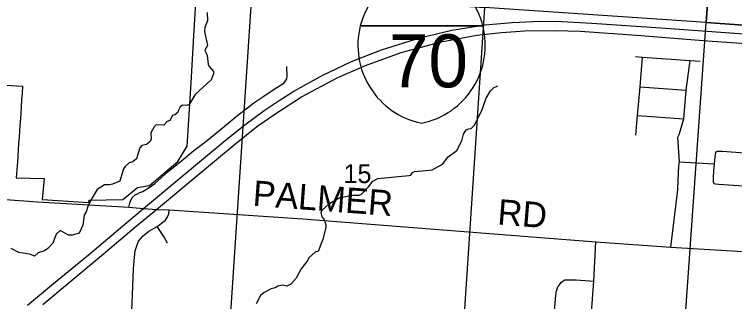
# Model space of a CAD drawing. Extents: x 0 to 34, y 0 to 22.
# Drawn here: x 4.853 to 6.46, y 18.458 to 19.099 of the extents above; entities that cross this region are included whole.
import ezdxf

# ---------------------------------------------------------------- set-up
doc = ezdxf.new("R2010")
doc.units = 0
for name, color, linetype in [('GM_X_Corporation', 7, 'Continuous'), ('GM_X_Interstate_Location', 7, 'Continuous'), ('GM_X_Interstate_Route', 7, 'Continuous'), ('GM_X_Interstate_Shield', 7, 'Continuous'), ('GM_X_Minor_River', 7, 'Continuous'), ('GM_X_Section_Text', 7, 'Continuous'), ('GM_X_Township_Road', 7, 'Continuous'), ('GM_X_Township_Road_Text', 7, 'Continuous')]:
    doc.layers.add(name, color=color, linetype=linetype)

msp = doc.modelspace()

# ---------------------------------------------------------------- linework, layer by layer
at = {"layer": 'GM_X_Corporation'}
for points in [[(5.9674, 20.1102), (6.4654, 20.076), (6.3967, 19.0805), (5.9022, 19.114)], [(6.4654, 20.076), (6.9844, 20.0383), (6.914, 19.0437), (6.3967, 19.0805)], [(5.3836, 19.1504), (5.9022, 19.114), (5.8356, 18.116), (5.3174, 18.1535)], [(6.3967, 19.0805), (6.914, 19.0437), (6.8357, 18.0433), (6.3257, 18.0804)]]:
    msp.add_lwpolyline(points, close=True, dxfattribs=at)
msp.add_lwpolyline([(4.7833, 18.9438), (4.8712, 18.9382), (4.8702, 18.9224), (4.8692, 18.9087), (4.8681, 18.892), (4.8672, 18.8783), (4.8663, 18.8653), (4.8653, 18.8516), (4.8644, 18.8379), (4.8635, 18.8242), (4.8625, 18.8105), (4.8616, 18.7968), (4.8606, 18.7831), (4.8605, 18.7807), (4.8597, 18.7694), (4.8573, 18.7339), (4.9194, 18.7323), (4.9153, 18.6853), (5.0193, 18.679), (5.0195, 18.6838), (5.0949, 18.6852), (5.1276, 18.7121), (5.1542, 18.7171), (5.2173, 18.7703), (5.2386, 18.8043), (5.2471, 18.9463), (5.2534, 19.0508), (5.2599, 19.1614)], dxfattribs=at)
at = {"layer": 'GM_X_Interstate_Route'}
for points in [[(4.8825, 18.4496), (4.9405, 18.4978), (5.0218, 18.5653), (5.09, 18.6223), (5.1411, 18.6657), (5.2176, 18.7294), (5.3229, 18.8173), (5.3672, 18.8525), (5.4103, 18.8841), (5.4436, 18.9067), (5.4765, 18.9277), (5.5415, 18.9634), (5.6053, 18.9934), (5.6721, 19.0197), (5.7573, 19.0464), (5.8288, 19.0633), (5.903, 19.0751), (5.9635, 19.0806), (6.0255, 19.0835), (6.0742, 19.083), (6.1416, 19.0793), (6.2952, 19.0686), (6.6043, 19.0467)], [(4.9162, 18.4512), (4.9754, 18.5005), (5.056, 18.5682), (5.125, 18.6259), (5.1701, 18.6632), (5.2466, 18.7269), (5.352, 18.8147), (5.3962, 18.85), (5.4361, 18.8778), (5.4937, 18.9146), (5.5748, 18.9576), (5.6362, 18.985), (5.7161, 19.0134), (5.8055, 19.0373), (5.8848, 19.0522), (5.9394, 19.0586), (5.9915, 19.0619), (6.0599, 19.0627), (6.1153, 19.0612), (6.2407, 19.0521), (6.3995, 19.0399), (6.6039, 19.0257)]]:
    msp.add_lwpolyline(points, dxfattribs=at)
at = {"layer": 'GM_X_Interstate_Shield'}
for p, q in [((5.6249, 19.0734), (5.8981, 19.0734)), ((5.8981, 19.0734), (5.6249, 19.0734)), ((5.8981, 19.0734), (5.6249, 19.0734))]:
    msp.add_line(p, q, dxfattribs=at)
for centre, start, end in [((5.797, 19.0298), 141.669, 165.8066), ((5.726, 19.0298), 14.1934, 38.331), ((5.797, 19.0298), 165.8066, 258.463), ((5.726, 19.0298), 281.537, 14.1934)]:
    msp.add_arc(centre, 0.1776, start, end, dxfattribs=at)
at = {"layer": 'GM_X_Minor_River'}
for points in [[(5.2834, 19.1026), (5.2838, 19.0844), (5.2819, 19.0794), (5.2777, 19.0692), (5.2773, 19.0605), (5.2837, 19.0293), (5.278, 19.0187), (5.2829, 19.0069), (5.2852, 18.9876), (5.2874, 18.9823), (5.2927, 18.9762), (5.2969, 18.9712), (5.2976, 18.9663), (5.2919, 18.9527), (5.2563, 18.9197), (5.2427, 18.8973), (5.2378, 18.8954), (5.2279, 18.8962), (5.223, 18.8924), (5.2188, 18.8852), (5.2173, 18.8799), (5.2112, 18.8746), (5.2059, 18.8734), (5.1995, 18.8617), (5.1942, 18.8594), (5.1862, 18.8518), (5.1696, 18.8522), (5.1647, 18.8481), (5.1575, 18.834), (5.1578, 18.8192), (5.1555, 18.8139), (5.148, 18.8082), (5.137, 18.806), (5.1332, 18.801), (5.1252, 18.776), (5.1169, 18.7699), (5.109, 18.7677), (5.0999, 18.7593), (5.0965, 18.754), (5.0881, 18.7263), (5.0722, 18.7195), (5.0658, 18.7184), (5.0537, 18.7184), (5.0378, 18.7078), (5.0241, 18.6858), (5.0165, 18.6698), (5.0131, 18.6577), (5.0089, 18.6509), (5.0055, 18.6281), (4.9975, 18.6103), (4.982, 18.6057), (4.9737, 18.6061), (4.9552, 18.616), (4.9464, 18.6084), (4.9385, 18.5879), (4.9275, 18.5758), (4.9199, 18.5713), (4.9063, 18.5663), (4.8976, 18.5591), (4.8896, 18.563), (4.8821, 18.5645), (4.8628, 18.5675), (4.8458, 18.5763)], [(5.5561, 18.6765), (5.5792, 18.6902), (5.608, 18.695), (5.622, 18.695), (5.6273, 18.6976), (5.6433, 18.7139), (5.6528, 18.7261), (5.6637, 18.7321), (5.7327, 18.7388), (5.7376, 18.7399), (5.741, 18.7456), (5.746, 18.7479), (5.7706, 18.7501), (5.7853, 18.752), (5.8085, 18.7641), (5.821, 18.7811), (5.8403, 18.7951), (5.851, 18.8167), (5.8552, 18.8312), (5.8609, 18.841), (5.8669, 18.8433), (5.8719, 18.844), (5.8791, 18.8505), (5.8958, 18.8842), (5.9057, 18.9115), (5.9152, 18.9282), (5.922, 18.9347), (5.9319, 18.9396)], [(5.5561, 18.6765), (5.5386, 18.6612), (5.5367, 18.6556), (5.539, 18.6472), (5.5442, 18.6407), (5.5476, 18.6293), (5.548, 18.6229), (5.5415, 18.5971), (5.5305, 18.5698), (5.5245, 18.5686), (5.5097, 18.5554), (5.5078, 18.5501), (5.4926, 18.5307), (5.4817, 18.5099), (5.4695, 18.4966), (5.4608, 18.492), (5.4514, 18.494), (5.4411, 18.4921), (5.4347, 18.4883), (5.4256, 18.486), (5.4101, 18.4777), (5.4022, 18.4716), (5.3927, 18.4523)]]:
    msp.add_lwpolyline(points, dxfattribs=at)
at = {"layer": 'GM_X_Township_Road'}
for p, q in [((6.2489, 18.9373), (6.3518, 18.9294)), ((6.2435, 18.8727), (6.3468, 18.8659))]:
    msp.add_line(p, q, dxfattribs=at)
for points in [[(6.2384, 19.0048), (6.2547, 19.0034), (6.3605, 18.9957), (6.383, 18.9941)], [(6.2392, 18.8294), (6.2435, 18.8727), (6.2489, 18.9373), (6.2547, 19.0034)], [(6.3335, 18.7091), (6.3356, 18.7617), (6.3368, 18.7693), (6.3333, 18.8245), (6.3359, 18.8306), (6.3389, 18.8401), (6.3468, 18.8659), (6.3518, 18.9294), (6.3605, 18.9957)], [(5.1086, 18.6685), (5.1105, 18.6772), (5.112, 18.6819), (5.1157, 18.69), (5.1225, 18.6958), (5.1279, 18.6984), (5.1328, 18.701), (5.1393, 18.7036), (5.1454, 18.7073), (5.1503, 18.7099), (5.1561, 18.7136), (5.166, 18.7215), (5.197, 18.7488), (5.2257, 18.7719), (5.2532, 18.7947), (5.2803, 18.8153), (5.3124, 18.8414), (5.3476, 18.871), (5.3728, 18.8904), (5.3874, 18.9016), (5.4076, 18.915), (5.4324, 18.9318), (5.4503, 18.9429), (5.4538, 18.9455), (5.4576, 18.9504), (5.4607, 18.9546), (5.4619, 18.961), (5.461, 18.9823)], [(6.5226, 18.7863), (6.432, 18.7926), (6.4259, 18.7924), (6.4206, 18.7924), (6.4169, 18.7907), (6.4162, 18.7863), (6.4157, 18.7802), (6.414, 18.7649), (6.4128, 18.7484), (6.4123, 18.7358), (6.4121, 18.7294), (6.4118, 18.7246), (6.4138, 18.7214), (6.4174, 18.7204), (6.425, 18.72), (6.4898, 18.7153)], [(6.3368, 18.7693), (6.3487, 18.769), (6.414, 18.7649)], [(4.3588, 18.7211), (4.6089, 18.7022), (4.6446, 18.6995), (4.7336, 18.6925), (4.7612, 18.6909), (4.9046, 18.6801), (5.1086, 18.6685), (5.1411, 18.6657), (5.1701, 18.6632), (5.1983, 18.6624), (5.4964, 18.642), (6.1506, 18.5908), (6.3173, 18.5789), (6.5773, 18.5635)], [(6.3173, 18.5789), (6.3334, 18.7071), (6.3335, 18.7091)], [(5.1096, 18.3549), (5.1161, 18.4533), (5.1188, 18.5308), (5.1212, 18.5566), (5.1225, 18.5713), (5.1262, 18.5823), (5.1302, 18.5923), (5.14, 18.6043), (5.1532, 18.6145), (5.1719, 18.6253), (5.1902, 18.6394), (5.1945, 18.6467), (5.1975, 18.6539), (5.1983, 18.6624)], [(5.1943, 18.588), (5.1863, 18.6027), (5.1719, 18.6253)], [(6.1334, 18.3343), (6.146, 18.5033), (6.1506, 18.5908)], [(6.0343, 18.1015), (6.0402, 18.2219), (6.0499, 18.3404), (6.0608, 18.4722), (6.0615, 18.4764), (6.0619, 18.4794), (6.063, 18.4828), (6.0645, 18.4882), (6.0664, 18.492), (6.069, 18.495), (6.0709, 18.4973), (6.0739, 18.5011), (6.0766, 18.5034), (6.0807, 18.5061), (6.0868, 18.5065), (6.0906, 18.5065), (6.0955, 18.5065), (6.1065, 18.5062), (6.146, 18.5033)]]:
    msp.add_lwpolyline(points, dxfattribs=at)

# ---------------------------------------------------------------- texts
at = {"layer": 'GM_X_Interstate_Location'}
for s in ['-', '.', ',']:
    msp.add_text(s, height=0.000189, dxfattribs=at).set_placement((5.7615, 18.9978))
msp.add_text('70', height=0.000189, rotation=0, dxfattribs=at).set_placement((5.7228, 18.9586))
at = {"layer": 'GM_X_Interstate_Shield'}
msp.add_text('70', height=0.11837, dxfattribs=at).set_placement((5.6888, 18.9358))
at = {"layer": 'GM_X_Section_Text'}
msp.add_text('15', height=0.04186, rotation=0, dxfattribs=at).set_placement((5.5874, 18.7222))
at = {"layer": 'GM_X_Township_Road_Text'}
for s, rotation, p in [('PALMER', 355.7569, (5.3835, 18.6716)), ('RD', 355.5623, (5.9295, 18.6299))]:
    msp.add_text(s, height=0.05682, rotation=rotation, dxfattribs=at).set_placement(p)

doc.saveas('drawing.dxf')
